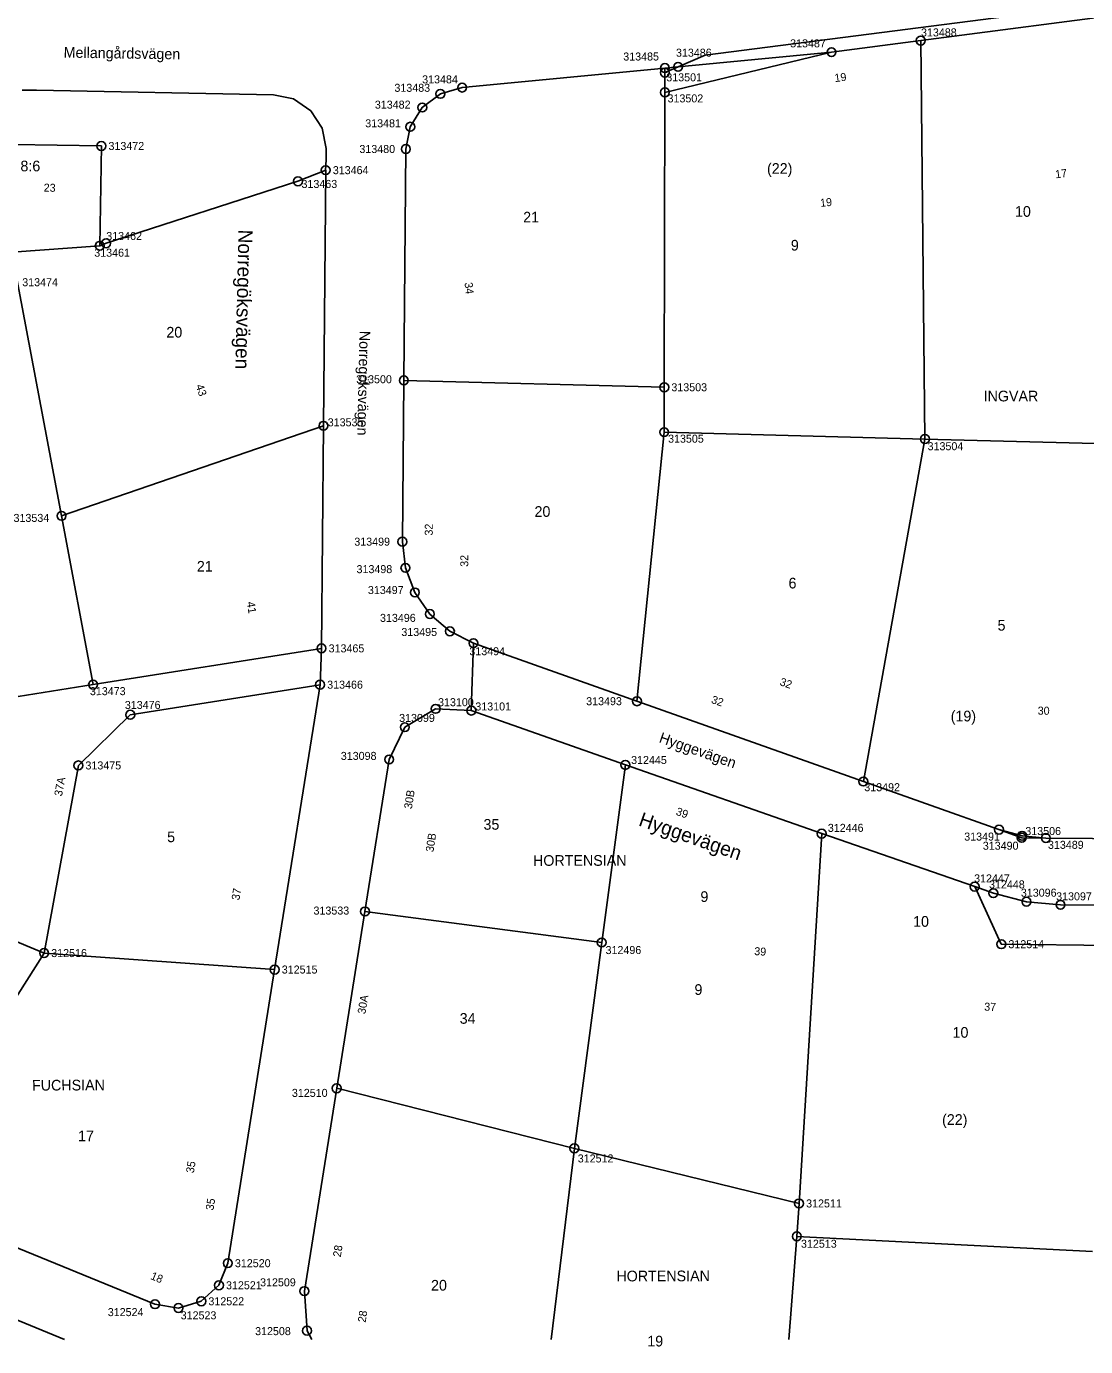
# Model space of a CAD drawing. Extents: x 141995 to 152570, y 6580184 to 6586000.
# Drawn here: x 142748 to 142867.1, y 6584999.2 to 6585147.6 of the extents above; entities that cross this region are included whole.
import ezdxf

# ---------------------------------------------------------------- set-up
doc = ezdxf.new("R2010")
doc.units = 0
for name, color, linetype in [('Level 10', 7, 'Continuous'), ('Level 13', 7, 'Continuous'), ('Level 40', 7, 'Continuous'), ('Level 42', 7, 'Continuous'), ('Level 43', 7, 'Continuous'), ('Level 5', 7, 'Continuous'), ('Level 50', 7, 'Continuous'), ('Level 51', 7, 'Continuous'), ('Level 52', 7, 'Continuous'), ('Level 53', 7, 'Continuous'), ('Level 54', 7, 'Continuous'), ('Level 55', 7, 'Continuous'), ('Level 58', 7, 'Continuous'), ('Level 59', 7, 'Continuous'), ('Level 6', 7, 'Continuous'), ('Level 7', 7, 'Continuous'), ('Level 9', 7, 'Continuous')]:
    doc.layers.add(name, color=color, linetype=linetype)

msp = doc.modelspace()

# ---------------------------------------------------------------- linework, layer by layer
at = {"layer": 'Level 10'}
for centre in [(142838.51, 6585144.73), (142848.55, 6585146.03), (142819.77, 6585142.94), (142819.77, 6585142.43), (142821.26, 6585143.08), (142796.97, 6585140.75), (142819.77, 6585140.21), (142794.52, 6585140.04), (142792.48, 6585138.51), (142791.13, 6585136.34), (142756.39, 6585134.18), (142790.64, 6585133.84), (142781.62, 6585131.46), (142778.5, 6585130.21), (142756.21, 6585122.96), (142756.92, 6585123.24), (142790.41, 6585107.82), (142819.7, 6585107.05), (142781.37, 6585102.72), (142819.69, 6585102), (142849.02, 6585101.23), (142751.91, 6585092.59), (142790.25, 6585089.69), (142790.59, 6585086.75), (142791.65, 6585083.98), (142793.34, 6585081.55), (142795.59, 6585079.61), (142798.24, 6585078.28), (142781.15, 6585077.69), (142755.46, 6585073.62), (142780.99, 6585073.61), (142793.98, 6585070.89), (142798, 6585070.7), (142816.63, 6585071.75), (142759.64, 6585070.23), (142790.52, 6585068.83), (142753.8, 6585064.53), (142788.76, 6585065.2), (142815.33, 6585064.59), (142842.1, 6585062.72), (142857.35, 6585057.31), (142837.41, 6585056.86), (142859.91, 6585056.4), (142859.95, 6585056.62), (142862.62, 6585056.37), (142854.62, 6585050.9), (142856.72, 6585050.17), (142860.44, 6585049.21), (142864.27, 6585048.86), (142786.04, 6585048.11), (142812.67, 6585044.62), (142857.61, 6585044.43), (142749.95, 6585043.43), (142775.88, 6585041.57), (142782.86, 6585028.23), (142809.59, 6585021.47), (142834.86, 6585015.28), (142834.61, 6585011.58), (142770.61, 6585008.56), (142769.61, 6585006.08), (142779.22, 6585005.42), (142762.42, 6585003.95), (142767.63, 6585004.28), (142765.06, 6585003.52), (142779.52, 6585000.97)]:
    msp.add_circle(centre, 0.5, dxfattribs=at)
at = {"layer": 'Level 13'}
for points in [[(142747.5, 6585140.46), (142749.11, 6585140.44)], [(142749.11, 6585140.44), (142775.75, 6585139.95)], [(142775.75, 6585139.95), (142778, 6585139.49)], [(142778, 6585139.49), (142779.94, 6585138.14)], [(142779.94, 6585138.14), (142781.21, 6585136.2)], [(142781.21, 6585136.2), (142781.66, 6585133.89)], [(142781.66, 6585133.89), (142781.66, 6585132.61)], [(142781.66, 6585132.61), (142781.6, 6585131.45)]]:
    msp.add_lwpolyline(points, dxfattribs=at)
at = {"layer": 'Level 5'}
for points in [[(142848.55, 6585146.03), (142873.36, 6585149.26)], [(142838.51, 6585144.73), (142848.55, 6585146.03)], [(142819.77, 6585140.21), (142838.51, 6585144.73)], [(142796.97, 6585140.75), (142819.77, 6585142.94)], [(142819.77, 6585142.94), (142819.77, 6585142.43)], [(142819.77, 6585142.43), (142819.77, 6585140.21)], [(142794.52, 6585140.04), (142796.97, 6585140.75)], [(142792.48, 6585138.51), (142794.52, 6585140.04)], [(142791.13, 6585136.34), (142792.48, 6585138.51)], [(142790.64, 6585133.84), (142791.13, 6585136.34)], [(142790.41, 6585107.82), (142790.64, 6585133.84)], [(142778.5, 6585130.21), (142781.62, 6585131.46)], [(142781.62, 6585131.46), (142781.37, 6585102.72)], [(142756.92, 6585123.24), (142778.5, 6585130.21)], [(142756.21, 6585122.96), (142746.34, 6585122.24)], [(142756.21, 6585122.96), (142756.92, 6585123.24)], [(142790.25, 6585089.69), (142790.41, 6585107.82)], [(142781.37, 6585102.72), (142781.15, 6585077.69)], [(142790.59, 6585086.75), (142790.25, 6585089.69)], [(142791.65, 6585083.98), (142790.59, 6585086.75)], [(142793.34, 6585081.55), (142791.65, 6585083.98)], [(142795.59, 6585079.61), (142793.34, 6585081.55)], [(142798.24, 6585078.28), (142795.59, 6585079.61)], [(142781.15, 6585077.69), (142780.99, 6585073.61)], [(142816.63, 6585071.75), (142798.24, 6585078.28)], [(142780.99, 6585073.61), (142775.88, 6585041.57)], [(142790.52, 6585068.83), (142793.98, 6585070.89)], [(142793.98, 6585070.89), (142798, 6585070.7)], [(142842.1, 6585062.72), (142816.63, 6585071.75)], [(142798, 6585070.7), (142815.33, 6585064.59)], [(142788.76, 6585065.2), (142790.52, 6585068.83)], [(142786.04, 6585048.11), (142788.76, 6585065.2)], [(142815.33, 6585064.59), (142837.41, 6585056.86)], [(142857.35, 6585057.31), (142842.1, 6585062.72)], [(142837.41, 6585056.86), (142854.62, 6585050.9)], [(142859.91, 6585056.4), (142857.35, 6585057.31)], [(142862.62, 6585056.37), (142859.91, 6585056.4)], [(142862.62, 6585056.37), (142873.1, 6585056.27)], [(142854.62, 6585050.9), (142857.61, 6585044.43)], [(142786.04, 6585048.11), (142782.86, 6585028.23)], [(142857.61, 6585044.43), (142870.01, 6585044.3)], [(142775.88, 6585041.57), (142770.61, 6585008.56)], [(142779.22, 6585005.42), (142782.86, 6585028.23)], [(142762.42, 6585003.95), (142737.53, 6585014.12)], [(142770.61, 6585008.56), (142769.61, 6585006.08)], [(142769.61, 6585006.08), (142767.63, 6585004.28)], [(142741.2, 6585004.52), (142752.26, 6585000)], [(142767.63, 6585004.28), (142765.06, 6585003.52)], [(142779.52, 6585000.97), (142779.22, 6585005.42)], [(142765.06, 6585003.52), (142762.42, 6585003.95)], [(142780.07, 6585000), (142779.52, 6585000.97)]]:
    msp.add_lwpolyline(points, dxfattribs=at)
at = {"layer": 'Level 6'}
for points in [[(142873.36, 6585149.26), (142848.55, 6585146.03), (142838.51, 6585144.73), (142821.26, 6585143.08), (142819.77, 6585142.94), (142796.97, 6585140.75), (142794.52, 6585140.04), (142792.48, 6585138.51), (142791.13, 6585136.34), (142790.64, 6585133.84), (142790.41, 6585107.82), (142790.25, 6585089.69), (142790.59, 6585086.75), (142791.65, 6585083.98), (142793.34, 6585081.55), (142795.59, 6585079.61), (142798.24, 6585078.28), (142816.63, 6585071.75), (142842.1, 6585062.72), (142857.35, 6585057.31), (142859.95, 6585056.62), (142862.62, 6585056.37), (142873.1, 6585056.27)], [(142737.53, 6585014.12), (142762.42, 6585003.95), (142765.06, 6585003.52), (142767.63, 6585004.28), (142769.61, 6585006.08), (142770.61, 6585008.56), (142775.88, 6585041.57), (142780.99, 6585073.61), (142781.15, 6585077.69), (142781.37, 6585102.72), (142781.62, 6585131.46), (142778.5, 6585130.21), (142756.92, 6585123.24), (142756.21, 6585122.96), (142756.39, 6585134.18), (142741.39, 6585134.42)], [(142870.29, 6585048.8), (142864.27, 6585048.86), (142860.44, 6585049.21), (142856.72, 6585050.17), (142854.62, 6585050.9), (142837.41, 6585056.86), (142815.33, 6585064.59), (142798, 6585070.7), (142793.98, 6585070.89), (142790.52, 6585068.83), (142788.76, 6585065.2), (142786.04, 6585048.11), (142782.86, 6585028.23), (142779.22, 6585005.42), (142779.52, 6585000.97), (142780.07, 6585000)], [(142752.26, 6585000), (142741.2, 6585004.52), (142733.89, 6585007.51), (142729.54, 6585010.75), (142715.38, 6585021.43), (142698.02, 6585034.52), (142692.4, 6585038.75), (142670.64, 6585055.16), (142670.47, 6585055.35), (142668.29, 6585057.08), (142664.6, 6585060.29), (142661.08, 6585063.65), (142658.18, 6585066.71), (142654.9, 6585069.02), (142651.02, 6585069.69), (142647.22, 6585068.65), (142636.86, 6585063.12), (142650.32, 6585038.48), (142653.83, 6585040.35), (142659.06, 6585034.42), (142674.11, 6585017.32), (142678.79, 6585012.03), (142689.39, 6585000)]]:
    msp.add_lwpolyline(points, dxfattribs=at)
at = {"layer": 'Level 7'}
for points in [[(142859.65, 6585148.93), (142824.31, 6585144.41)], [(142849.02, 6585101.23), (142848.55, 6585146.03)], [(142824.31, 6585144.41), (142821.26, 6585143.08)], [(142819.77, 6585142.43), (142821.26, 6585143.08)], [(142819.77, 6585140.21), (142819.7, 6585107.05)], [(142741.39, 6585134.42), (142756.39, 6585134.18)], [(142756.39, 6585134.18), (142756.21, 6585122.96)], [(142751.91, 6585092.59), (142746.9, 6585119.24)], [(142819.7, 6585107.05), (142790.41, 6585107.82)], [(142819.69, 6585102), (142819.7, 6585107.05)], [(142781.37, 6585102.72), (142751.91, 6585092.59)], [(142816.63, 6585071.75), (142819.69, 6585102)], [(142849.02, 6585101.23), (142819.69, 6585102)], [(142842.1, 6585062.72), (142849.02, 6585101.23)], [(142849.02, 6585101.23), (142874.11, 6585100.59)], [(142751.91, 6585092.59), (142755.46, 6585073.62)], [(142781.15, 6585077.69), (142755.46, 6585073.62)], [(142798, 6585070.7), (142798.24, 6585078.28)], [(142732.94, 6585070.03), (142755.46, 6585073.62)], [(142780.99, 6585073.61), (142759.64, 6585070.23)], [(142759.64, 6585070.23), (142753.8, 6585064.53)], [(142753.8, 6585064.53), (142749.95, 6585043.43)], [(142815.33, 6585064.59), (142812.67, 6585044.62)], [(142837.41, 6585056.86), (142834.86, 6585015.28)], [(142725.92, 6585053.48), (142749.95, 6585043.43)], [(142786.04, 6585048.11), (142812.67, 6585044.62)], [(142812.67, 6585044.62), (142809.59, 6585021.47)], [(142749.95, 6585043.43), (142733.33, 6585017.29)], [(142775.88, 6585041.57), (142749.95, 6585043.43)], [(142809.59, 6585021.47), (142782.86, 6585028.23)], [(142806.97, 6585000), (142809.59, 6585021.47)], [(142834.86, 6585015.28), (142809.59, 6585021.47)], [(142834.61, 6585011.58), (142834.86, 6585015.28)], [(142833.72, 6585000), (142834.61, 6585011.58)], [(142834.61, 6585011.58), (142867.86, 6585009.89)]]:
    msp.add_lwpolyline(points, dxfattribs=at)
at = {"layer": 'Level 9'}
for points in [[(142819.77, 6585142.94), (142819.77, 6585142.43)], [(142819.77, 6585142.43), (142819.77, 6585140.21)]]:
    msp.add_lwpolyline(points, dxfattribs=at)

# ---------------------------------------------------------------- texts
at = {"layer": 'Level 40'}
for s, rotation, p in [('Mellangårdsvägen', 359.1123, (142752.14, 6585144.12)), ('Hyggevägen', 340.705, (142819.03, 6585067.16))]:
    msp.add_text(s, height=1.2, rotation=rotation, dxfattribs=at).set_placement(p)
at = {"layer": 'Level 42'}
msp.add_text('Norregöksvägen', height=1.2, rotation=268.7109, dxfattribs=at).set_placement((142785.43, 6585113.41))
at = {"layer": 'Level 43'}
for s, rotation, p in [('Norregöksvägen', 268.7109, (142771.81, 6585124.79)), ('Hyggevägen', 340.706, (142816.72, 6585057.8))]:
    msp.add_text(s, height=1.6, rotation=rotation, dxfattribs=at).set_placement(p)
at = {"layer": 'Level 50'}
msp.add_text('INGVAR', height=1.2, rotation=0.0514, dxfattribs=at).set_placement((142855.62, 6585105.46))
at = {"layer": 'Level 51'}
for s, rotation, p in [('8:6', 0.0514, (142747.29, 6585131.33)), ('10', 0.0514, (142859.15, 6585126.22)), ('21', 0.0514, (142803.83, 6585125.58)), ('9', 0.0514, (142833.94, 6585122.42)), ('20', 0.0514, (142763.7, 6585112.64)), ('20', 0.0514, (142805.11, 6585092.48)), ('21', 0.0514, (142767.13, 6585086.32)), ('6', 0.0514, (142833.68, 6585084.43)), ('5', 0.0514, (142857.19, 6585079.69)), ('35', 0.0514, (142799.37, 6585057.3)), ('5', 0.0514, (142763.79, 6585055.9)), ('9', 0.0514, (142823.1, 6585038.73)), ('34', 0.0514, (142796.69, 6585035.48)), ('10', 0.1764, (142852.13, 6585033.91)), ('17', 0.0514, (142753.77, 6585022.27)), ('20', 0.0514, (142793.47, 6585005.48)), ('19', 0.0514, (142817.79, 6584999.2))]:
    msp.add_text(s, height=1.2, rotation=rotation, dxfattribs=at).set_placement(p)
at = {"layer": 'Level 52'}
for s, rotation, p in [('(22)', 0.0514, (142831.26, 6585131.05)), ('(19)', 0.0514, (142851.92, 6585069.48)), ('(22)', 0.1764, (142850.95, 6585024.11))]:
    msp.add_text(s, height=1.2, rotation=rotation, dxfattribs=at).set_placement(p)
at = {"layer": 'Level 53'}
for s, p in [('313488', (142848.58, 6585146.5)), ('313486', (142821.02, 6585144.22)), ('313487', (142833.86, 6585145.27)), ('313485', (142815.09, 6585143.79)), ('313501', (142819.93, 6585141.45)), ('313483', (142789.35, 6585140.27)), ('313484', (142792.47, 6585141.22)), ('313482', (142787.15, 6585138.38)), ('313502', (142820.07, 6585139.08)), ('313481', (142786.07, 6585136.28)), ('313472', (142757.19, 6585133.73)), ('313480', (142785.41, 6585133.39)), ('313464', (142782.42, 6585131.01)), ('313463', (142778.9, 6585129.46)), ('313462', (142756.94, 6585123.61)), ('313461', (142755.59, 6585121.73)), ('313474', (142747.49, 6585118.41)), ('313500', (142785.05, 6585107.5)), ('313503', (142820.5, 6585106.6)), ('313535', (142781.85, 6585102.66)), ('313505', (142820.13, 6585100.82)), ('313504', (142849.32, 6585099.97)), ('313534', (142746.51, 6585091.91)), ('313499', (142784.84, 6585089.24)), ('313498', (142785.09, 6585086.15)), ('313497', (142786.37, 6585083.8)), ('313496', (142787.73, 6585080.67)), ('313495', (142790.13, 6585079.08)), ('313465', (142781.95, 6585077.24)), ('313494', (142797.78, 6585076.92)), ('313466', (142781.79, 6585073.16)), ('313473', (142755.1, 6585072.43)), ('313476', (142759.03, 6585070.88)), ('313100', (142794.26, 6585071.19)), ('313101', (142798.45, 6585070.71)), ('313493', (142810.92, 6585071.3)), ('313099', (142789.88, 6585069.42)), ('313475', (142754.6, 6585064.08)), ('313098', (142783.32, 6585065.15)), ('312445', (142815.97, 6585064.69)), ('313492', (142842.2, 6585061.63)), ('312446', (142838.1, 6585057.06)), ('313506', (142860.31, 6585056.7)), ('313491', (142853.44, 6585056.08)), ('313489', (142862.86, 6585055.15)), ('313490', (142855.53, 6585055.05)), ('312447', (142854.55, 6585051.38)), ('312448', (142856.23, 6585050.7)), ('313096', (142859.81, 6585049.77)), ('313097', (142863.78, 6585049.36)), ('313533', (142780.25, 6585047.76)), ('312496', (142813.1, 6585043.32)), ('312514', (142858.41, 6585043.98)), ('312516', (142750.75, 6585042.98)), ('312515', (142776.68, 6585041.13)), ('312510', (142777.82, 6585027.26)), ('312512', (142809.97, 6585019.89)), ('312511', (142835.66, 6585014.83)), ('312513', (142835.08, 6585010.3)), ('312520', (142771.41, 6585008.11)), ('312521', (142770.41, 6585005.63)), ('312509', (142774.24, 6585005.96)), ('312522', (142768.43, 6585003.83)), ('312524', (142757.11, 6585002.61)), ('312523', (142765.31, 6585002.25)), ('312508', (142773.68, 6585000.47))]:
    msp.add_text(s, height=0.9, rotation=0.0514, dxfattribs=at).set_placement(p)
at = {"layer": 'Level 54'}
for s, rotation, p in [('17', 7.4004, (142863.73, 6585130.54)), ('23', 358.9493, (142749.9, 6585129.05)), ('19', 5.4814, (142837.27, 6585127.33)), ('34', 277.0298, (142797.23, 6585118.8)), ('43', 288.8528, (142766.99, 6585107.22)), ('32', 89.7709, (142797.66, 6585086.86)), ('41', 279.0158, (142772.74, 6585082.88)), ('32', 341.016, (142832.62, 6585073.57)), ('30', 359.4153, (142861.7, 6585070.24)), ('37A', 79.6911, (142751.96, 6585061.02)), ('30B', 81.541, (142793.74, 6585054.74)), ('37', 80.936, (142771.91, 6585049.33)), ('39', 356.5023, (142829.8, 6585043.21)), ('30A', 80.936, (142786.08, 6585036.53)), ('37', 358.4983, (142855.68, 6585036.96)), ('35', 80.741, (142766.78, 6585018.64)), ('28', 81.746, (142786.11, 6585001.85))]:
    msp.add_text(s, height=0.9, rotation=rotation, dxfattribs=at).set_placement(p)
at = {"layer": 'Level 55'}
for s, rotation, p in [('19', 7.3734, (142838.91, 6585141.36)), ('32', 89.4869, (142793.66, 6585090.37)), ('32', 341.016, (142824.91, 6585071.57)), ('30B', 80.935, (142791.31, 6585059.59)), ('39', 340.527, (142820.93, 6585059)), ('35', 80.741, (142768.99, 6585014.46)), ('28', 80.927, (142783.31, 6585009.2)), ('18', 337.4449, (142761.85, 6585006.8))]:
    msp.add_text(s, height=0.9, rotation=rotation, dxfattribs=at).set_placement(p)
at = {"layer": 'Level 58'}
for s, rotation, p in [('HORTENSIAN', 0.0514, (142804.94, 6585053.24)), ('FUCHSIAN', 0.1764, (142748.59, 6585027.97)), ('HORTENSIAN', 0.1764, (142814.32, 6585006.51))]:
    msp.add_text(s, height=1.2, rotation=rotation, dxfattribs=at).set_placement(p)
at = {"layer": 'Level 59'}
for s, p in [('9', (142823.77, 6585049.18)), ('10', (142847.69, 6585046.39))]:
    msp.add_text(s, height=1.2, rotation=0.0514, dxfattribs=at).set_placement(p)

doc.saveas('drawing.dxf')
